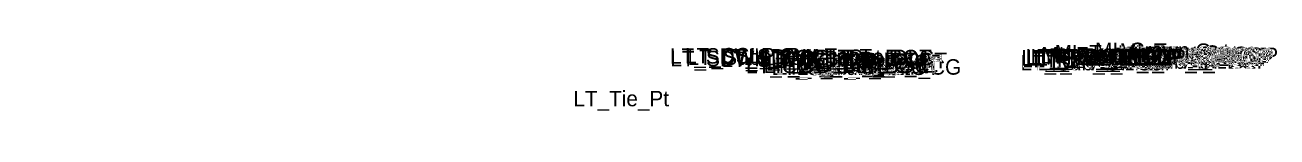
# Model space of a CAD drawing. Extents: x 0 to 4229, y -1 to 9523.
# Drawn here: x 3000 to 3161.6, y 6500 to 6510 of the extents above; entities that cross this region are included whole.
import ezdxf

# ---------------------------------------------------------------- set-up
doc = ezdxf.new("R2010")
doc.units = 0
doc.layers.add('Default', color=7, linetype='Continuous')

msp = doc.modelspace()

# ---------------------------------------------------------------- texts
at = {"layer": 'Default'}
for s, height, p in [('LT_SDWK_Out_Top', 2, (3083.24, 6507.25)), ('LT_SDWK_Out_Bot', 2, (3083.27, 6506.91)), ('LT_CSLP_Pnt', 2, (3085.17, 6507.28)), ('LT_Sub_Trench_Out_DLT', 2, (3085.49, 6507.08)), ('LT_SDWK_In_Top', 2, (3089.86, 6507.15)), ('LT_CG_Top_Face', 2, (3094.76, 6507.04)), ('LT_CG_Top_BOC', 2, (3095.28, 6507.04)), ('LT_PV2_OEEOP', 2, (3128.56, 6507)), ('LT_PV1_OEEOP', 2, (3129.12, 6507.13)), ('LT_PV2_IEEOP', 2, (3129.2, 6507)), ('LT_PV1_IEEOP', 2, (3129.77, 6507.13)), ('LT_PV2_PGL1', 2, (3130.13, 6507)), ('LT_PV2_PGL', 2, (3130.46, 6507)), ('LT_PV1_PGL', 2, (3131.03, 6507.25)), ('MI_Face In', 2, (3131.15, 6507.42)), ('MI_Bot In', 2, (3132.13, 6507.25)), ('MI_Top In', 2, (3132.86, 6507.67)), ('MI_Crown', 2, (3138.08, 6507.97)), ('RT_PV2_OEEOP', 2, (3140.02, 6507.2)), ('RT_PV3_OEEOP', 2, (3140.02, 6506.95)), ('RT_PV1_OEEOP', 2, (3140.59, 6507.33)), ('RT_PV2_IEEOP', 2, (3140.66, 6507.2)), ('MI_Face Out', 2, (3141.02, 6507.62)), ('MI_Top Out', 2, (3141.23, 6507.87)), ('RT_PV1_IEEOP', 2, (3141.23, 6507.33)), ('RT_PV2_PGL1', 2, (3141.59, 6507.2)), ('RT_PV3_PGL1', 2, (3141.59, 6506.95)), ('RT_PV2_PGL', 2, (3141.92, 6507.2)), ('MI_Bot Out', 2, (3142.02, 6507.45)), ('RT_PV1_PGL', 2, (3142.49, 6507.45)), ('LT_SDWK_In_Bot', 2, (3089.89, 6506.81)), ('LT_CG1_Shelf_Out', 2, (3093.05, 6506.01)), ('LT_CG_Bot_BOC', 2, (3095.31, 6506.02)), ('LT_CG_Top_Gut', 2, (3095.74, 6506.54)), ('LT_Sub_OEOP', 2, (3096.36, 6505.76)), ('LT_Sub_OEOT_CG', 2, (3096.87, 6505.82)), ('LT_CG_Bot_IE', 2, (3099.41, 6506.07)), ('LT_Sub_OEOT', 2, (3099.58, 6505.78)), ('LT_PV2_OEOT', 2, (3099.67, 6506.41)), ('LT_PV3_OEOT', 2, (3099.67, 6506.16)), ('LT_PV1_OEOT', 2, (3100.24, 6506.66)), ('LT_Sub_OEEOP', 2, (3128.46, 6506.38)), ('LT_PV3_OEEOP', 2, (3128.56, 6506.75)), ('LT_PV3_PGL1', 2, (3130.13, 6506.75)), ('LT_PV4_PGL', 2, (3130.46, 6506.38)), ('RT_Sub_OEEOP', 2, (3139.92, 6506.58)), ('RT_PV4_PGL', 2, (3141.92, 6506.58)), ('LT_Tie_Pt', 2, (3070.76, 6501.72)), ('-', 0.0001, (3000, 6500)), ('-', 0.0001, (3000, 6500)), ('-', 0.0001, (3000, 6500)), ('-', 0.0001, (3000, 6500)), ('-', 0.0001, (3000, 6500)), ('-', 0.0001, (3000, 6500)), ('-', 0.0001, (3000, 6500))]:
    msp.add_text(s, height=height, dxfattribs=at).set_placement(p)

doc.saveas('drawing.dxf')
